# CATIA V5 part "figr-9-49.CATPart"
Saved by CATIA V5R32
Part number: Part1
Bounding box of the stored display mesh (mm): x -53.48 to 62.241, y -50 to 50, z -57.709 to 133.109
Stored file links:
  D:\PROJECTS\Project 2022\CATIA V5 6R 2022\Resources\Part Files\c09_catia_v5_6r2022_prt\c09_catia_v5_6r2022_prt\figr-9-49.CATPart
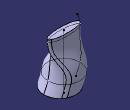
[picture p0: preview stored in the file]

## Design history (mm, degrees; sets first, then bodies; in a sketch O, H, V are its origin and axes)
Body1 (main body)
  Plane1: type Offset, RefPlane xy-plane, Offset 103
  Sketch1 on Plane1, origin (0, 0, 103), H (1, 0, 0), V (0, 1, 0)
    ellipse A1 centre (0, 0) semi-axes 50, 13.2069 rotation 0
    point P1 (50, 0)
    "Radius" A1 = 50
    coincidence: P1 H, A1 P1
  Extremum1: Reference Sketch1, Direction (1, 2, 3)
  Sketch2 on xy-plane, origin (0, 0, 0), H (1, 0, 0), V (0, 1, 0)
    circle A1 centre (0, 0) radius 50
    radius A1 = 50
  Extremum2: Reference Sketch2, Direction (1, 2, 3)
  Sketch3 on zx-plane, origin (0, 0, 0), H (-1, 0, 0), V (0, 0, 1)
    spline S1 through (37.7591, -31.0289) (41.8235, -21.251) (50, 0) (49.8084, 85.7657) (50, 103) (41.6255, 133.1089)
    reference projected line E1 (-50, 103) -> (50, 103) from Sketch1.A1
    point P1 (50, 0)
    point P2 (50, 103)
    distance V P1 = 50
    distance P2 V = 50
    coincidence: P1 H, P2 E1
  Sketch4 on zx-plane, origin (0, 0, 0), H (-1, 0, 0), V (0, 0, 1)
    line L1 (0, 111.062) -> (0, -57.7094)
    point P1 (0, 111.062)
    coincidence: P1 V
    vertical: L1 V
  Loft1: solid, Sections (Sketch1; Sketch2), Spine Sketch4, Guides Sketch3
